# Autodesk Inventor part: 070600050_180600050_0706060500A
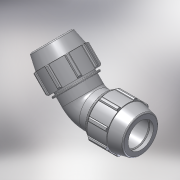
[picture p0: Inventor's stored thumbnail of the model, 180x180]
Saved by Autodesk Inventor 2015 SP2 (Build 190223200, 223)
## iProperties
Created: 2017-02
Part Number: 070600050_180600050_0706060500A
Material: PVC-Piping
Description: PLASSON 45° ELBOW 50-50
Document SubType Name: Modeling
Designer: KIM
Mass: 92.6774 g
Surface Area: 199.44 cm^2
Volume: 66.1981 cm^3
Density: 1.4 g/cm^3
Appearance: Smooth - White
Author: KIM
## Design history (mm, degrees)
derived "07060.ipt"
feature "Solid1::07060.ipt"
tag "TaggingFeature1"
body "Solid1"
other parameters: "d4" = 9.16667, "d5" = 27.5, "d7" = 96, "d9" = 15.71429, "d11" = 3.66667, "d13" = 120 deg, "d14" = 75, "d15" = 12 deg, "d16" = 83.52, "d18" = 2.5, "d19" = 35 deg, "d20" = 17.5 deg, "d21" = 89.28, "d23" = 0, "d25" = 360 deg, "d27" = 1.92, "d33" = 1, "d42" = 40.7, "d43" = 2.88, "d46" = 1.5, "d59" = 135 deg, "d63" = 93, "d67" = 72, "d68" = 3.66667, "d72" = 1.5, "d73" = 0, "d74" = 0, "E_" = 96, "l_" = 93
